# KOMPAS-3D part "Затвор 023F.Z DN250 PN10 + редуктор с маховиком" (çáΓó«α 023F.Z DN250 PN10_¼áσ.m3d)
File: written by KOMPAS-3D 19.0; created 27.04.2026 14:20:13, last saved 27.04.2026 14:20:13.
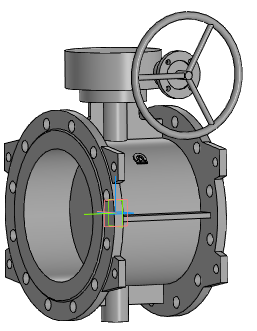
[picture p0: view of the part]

Document properties: Полное имя файла: ..\..\Затвор 023F.Z DN200-DN1600_с маховиком\Затвор 023F.Z DN250 PN10 + редуктор с маховиком.a3d

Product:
- Part/product: Затвор 023F.Z DN250 PN10 + редуктор с маховиком
    Масса: 74.5998

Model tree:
1. Операция без истории:1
